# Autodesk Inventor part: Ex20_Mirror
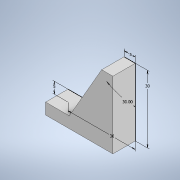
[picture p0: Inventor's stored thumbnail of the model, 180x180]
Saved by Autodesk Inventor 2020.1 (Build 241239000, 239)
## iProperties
Created: 2019-11
Part Number: Ex20_Mirror
Material: Generic
Document SubType Name: Modeling
Designer: Synergysoft Dell02
Density: 1 g/cm^3
Appearance: Default
Author: Synergysoft Dell02
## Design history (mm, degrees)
sketch "Sketch1"
  geometry: L1 (0, 30)-(-5, 30); L2 (-5, 30)-(-19.434, 5); L3 (-19.434, 5)-(-30, 5); L4 (-30, 5)-(-30, 0); L5 (-30, 0)-(0, 0); L6 (0, 0)-(0, 30)
  constraints: 12 end point, 3 perpendicular, 1 horizontal, 1 parallel
  dimensions: "d0" = 5 distance between parallel lines of L5 L3; "d1" = 30 deg angle of L6 L2; "d2" = 30 distance of L5.end L1.start; "d3" = 30 distance between parallel lines of L6 L4; "d4" = 5 distance of L1.start L1.end
extrude "Extrusion1" new body sketch "Sketch1" distance "d5" = 10; taper "d6" = 0 deg
body "Solid1"
